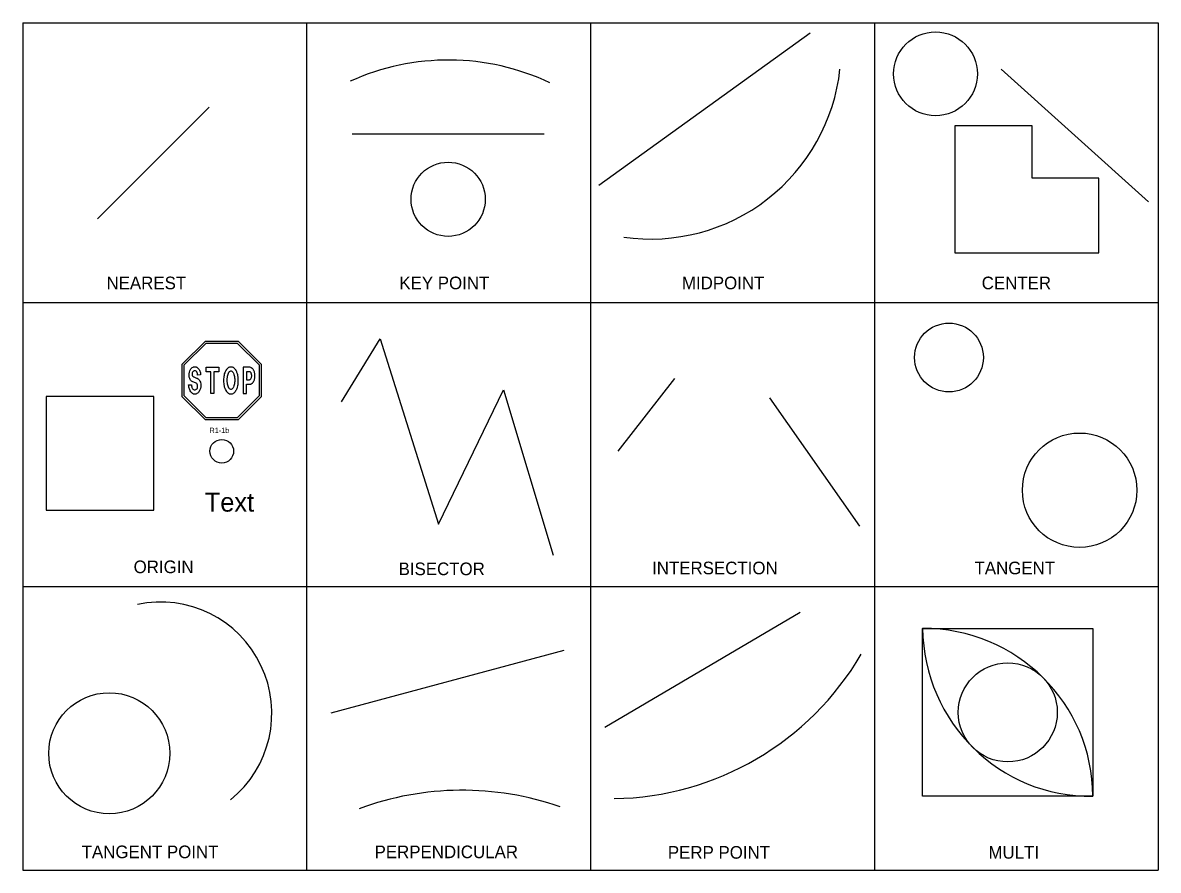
# Model space of a CAD drawing. Extents: x 0 to 180, y 0 to 134.
import ezdxf

# ---------------------------------------------------------------- set-up
doc = ezdxf.new("R2010")
doc.units = 0
for name, color, linetype in [('Default', 7, 'Continuous'), ('Level 1', 7, 'Continuous'), ('Level 2', 7, 'Continuous'), ('Level 3', 7, 'Continuous')]:
    doc.layers.add(name, color=color, linetype=linetype)

# ---------------------------------------------------------------- blocks, each defined once
blk = doc.blocks.new('R11B')
at = {"layer": 'Default'}
for p, q in [((-1.25, 2.762), (-0.518, 3.494)), ((-1.187, 2.736), (-0.492, 3.431)), ((-0.518, 3.494), (0.518, 3.494)), ((-0.492, 3.431), (0.492, 3.431)), ((0.492, 3.431), (1.187, 2.736)), ((0.518, 3.494), (1.25, 2.762)), ((-1.25, 1.726), (-1.25, 2.762)), ((-1.187, 1.752), (-1.187, 2.736)), ((1.187, 2.736), (1.187, 1.752)), ((1.25, 2.762), (1.25, 1.726)), ((-0.518, 0.994), (-1.25, 1.726)), ((-0.492, 1.056), (-1.187, 1.752)), ((1.187, 1.752), (0.492, 1.056)), ((1.25, 1.726), (0.518, 0.994)), ((0.518, 0.994), (-0.518, 0.994)), ((0.492, 1.056), (-0.492, 1.056))]:
    blk.add_line(p, q, dxfattribs=at)
for points in [[(-0.764, 2.044), (-0.764, 2.063), (-0.764, 2.096), (-0.775, 2.129), (-0.795, 2.149), (-0.814, 2.162), (-0.937, 2.214), (-0.96, 2.227), (-0.986, 2.254), (-1.002, 2.28), (-1.017, 2.306), (-1.029, 2.352), (-1.033, 2.392), (-1.033, 2.451), (-1.025, 2.503), (-1.013, 2.549), (-0.994, 2.588), (-0.979, 2.608)], [(-0.979, 2.608), (-0.967, 2.621), (-0.956, 2.634), (-0.948, 2.641), (-0.933, 2.654), (-0.91, 2.667), (-0.894, 2.674), (-0.867, 2.68), (-0.86, 2.68), (-0.844, 2.68), (-0.814, 2.674), (-0.802, 2.667), (-0.791, 2.661), (-0.772, 2.647), (-0.756, 2.634), (-0.748, 2.628), (-0.737, 2.615)], [(-0.764, 2.411), (-0.768, 2.464), (-0.775, 2.49), (-0.787, 2.516), (-0.798, 2.529), (-0.814, 2.542), (-0.837, 2.549), (-0.86, 2.549), (-0.879, 2.549), (-0.891, 2.542), (-0.906, 2.529), (-0.925, 2.51), (-0.937, 2.49), (-0.94, 2.464), (-0.94, 2.444)], [(-0.737, 2.615), (-0.718, 2.588), (-0.706, 2.569), (-0.695, 2.536), (-0.687, 2.516), (-0.679, 2.483), (-0.676, 2.451), (-0.672, 2.418), (-0.764, 2.411)], [(-0.499, 2.661), (-0.096, 2.661), (-0.096, 2.523), (-0.246, 2.523), (-0.246, 1.827), (-0.349, 1.827), (-0.349, 2.523), (-0.499, 2.523), (-0.499, 2.661)], [(0.069, 2.241), (0.069, 2.26), (0.069, 2.293), (0.073, 2.339), (0.077, 2.378), (0.084, 2.411), (0.092, 2.451), (0.104, 2.483), (0.111, 2.51), (0.119, 2.529), (0.13, 2.549), (0.157, 2.595), (0.161, 2.602), (0.173, 2.615), (0.184, 2.628), (0.196, 2.641), (0.203, 2.647), (0.223, 2.661), (0.238, 2.667), (0.253, 2.674), (0.292, 2.68)], [(0.173, 2.254), (0.173, 2.267), (0.173, 2.293), (0.173, 2.313), (0.177, 2.339), (0.18, 2.365), (0.184, 2.385), (0.188, 2.411), (0.2, 2.444), (0.211, 2.477), (0.215, 2.483), (0.223, 2.497), (0.23, 2.51), (0.238, 2.516), (0.249, 2.529), (0.269, 2.542), (0.284, 2.549), (0.296, 2.549), (0.303, 2.549), (0.315, 2.542), (0.326, 2.536), (0.342, 2.523), (0.361, 2.497), (0.372, 2.477), (0.388, 2.437), (0.395, 2.405), (0.403, 2.365), (0.407, 2.332), (0.411, 2.3), (0.411, 2.267), (0.411, 2.254)], [(0.288, 2.68), (0.307, 2.68), (0.334, 2.674), (0.349, 2.667), (0.361, 2.661), (0.388, 2.641), (0.411, 2.615), (0.43, 2.588), (0.453, 2.549), (0.464, 2.529), (0.472, 2.51), (0.48, 2.483), (0.487, 2.464), (0.495, 2.431), (0.503, 2.392), (0.507, 2.365), (0.51, 2.339), (0.514, 2.3), (0.514, 2.28), (0.514, 2.241)], [(0.894, 2.661), (0.683, 2.661), (0.683, 1.827), (0.787, 1.827), (0.787, 2.123), (0.894, 2.123)], [(0.871, 2.523), (0.787, 2.523), (0.787, 2.267), (0.871, 2.267)], [(0.871, 2.267), (0.879, 2.267), (0.894, 2.273), (0.906, 2.28), (0.914, 2.287), (0.925, 2.3), (0.933, 2.313), (0.937, 2.319), (0.944, 2.339), (0.948, 2.359), (0.952, 2.385), (0.952, 2.398), (0.948, 2.431), (0.944, 2.451), (0.937, 2.47), (0.929, 2.483), (0.921, 2.497), (0.914, 2.503), (0.906, 2.51), (0.898, 2.516), (0.879, 2.523), (0.875, 2.523), (0.871, 2.523)], [(0.894, 2.123), (0.917, 2.129), (0.933, 2.136), (0.944, 2.142), (0.956, 2.149), (0.963, 2.155), (0.971, 2.162), (0.983, 2.175), (0.994, 2.188), (1.002, 2.201), (1.01, 2.214), (1.017, 2.227), (1.025, 2.247), (1.033, 2.267), (1.036, 2.28), (1.04, 2.293), (1.044, 2.313), (1.048, 2.332), (1.052, 2.365), (1.052, 2.385), (1.052, 2.411), (1.048, 2.444), (1.048, 2.451), (1.044, 2.47), (1.04, 2.49), (1.033, 2.516), (1.025, 2.536), (1.017, 2.556), (1.01, 2.569), (1.002, 2.582), (0.994, 2.595), (0.983, 2.608), (0.971, 2.621), (0.963, 2.628), (0.956, 2.634), (0.944, 2.641), (0.937, 2.647), (0.917, 2.654), (0.894, 2.661)], [(-0.94, 2.444), (-0.94, 2.424), (-0.933, 2.405), (-0.925, 2.392), (-0.914, 2.378), (-0.887, 2.359), (-0.802, 2.319), (-0.783, 2.313), (-0.752, 2.3), (-0.729, 2.28), (-0.714, 2.26), (-0.702, 2.247), (-0.691, 2.221), (-0.679, 2.195), (-0.676, 2.175), (-0.668, 2.136), (-0.664, 2.109), (-0.664, 2.09), (-0.664, 2.057), (-0.668, 2.024), (-0.672, 1.998), (-0.676, 1.991)], [(0.514, 2.241), (0.514, 2.195), (0.51, 2.136), (0.507, 2.109), (0.499, 2.077), (0.491, 2.037), (0.484, 2.011), (0.476, 1.991), (0.464, 1.958), (0.453, 1.939), (0.441, 1.913), (0.422, 1.886), (0.411, 1.873), (0.399, 1.86), (0.38, 1.84), (0.361, 1.827), (0.349, 1.821), (0.326, 1.814), (0.303, 1.808), (0.296, 1.808), (0.276, 1.808), (0.249, 1.814), (0.238, 1.821), (0.223, 1.827), (0.215, 1.834), (0.203, 1.84), (0.196, 1.847), (0.184, 1.86), (0.165, 1.88), (0.157, 1.893), (0.127, 1.945), (0.119, 1.958), (0.107, 1.991), (0.1, 2.011), (0.092, 2.037), (0.084, 2.077), (0.081, 2.096), (0.077, 2.123), (0.073, 2.149), (0.069, 2.188), (0.069, 2.221), (0.069, 2.241)], [(0.296, 1.958), (0.284, 1.958), (0.269, 1.965), (0.249, 1.978), (0.238, 1.991), (0.23, 1.998), (0.223, 2.011), (0.215, 2.024), (0.211, 2.031), (0.2, 2.063), (0.188, 2.096), (0.184, 2.123), (0.18, 2.142), (0.177, 2.168), (0.173, 2.195), (0.173, 2.214), (0.173, 2.241), (0.173, 2.254)], [(0.411, 2.254), (0.411, 2.241), (0.411, 2.208), (0.407, 2.175), (0.403, 2.142), (0.395, 2.103), (0.388, 2.07), (0.372, 2.031), (0.361, 2.011), (0.342, 1.985), (0.326, 1.972), (0.315, 1.965), (0.303, 1.958), (0.296, 1.958)], [(-1.052, 2.103), (-0.956, 2.109), (-0.956, 2.09)], [(-0.676, 1.991), (-0.683, 1.972), (-0.691, 1.952), (-0.702, 1.926), (-0.71, 1.913), (-0.722, 1.893), (-0.729, 1.88), (-0.741, 1.867), (-0.752, 1.853), (-0.768, 1.84), (-0.787, 1.827), (-0.798, 1.821), (-0.818, 1.814), (-0.844, 1.808), (-0.856, 1.808), (-0.867, 1.808), (-0.894, 1.814), (-0.91, 1.821), (-0.917, 1.827), (-0.929, 1.834), (-0.937, 1.84), (-0.952, 1.853), (-0.96, 1.86), (-0.979, 1.886), (-0.998, 1.913), (-1.013, 1.945), (-1.017, 1.952), (-1.025, 1.978), (-1.033, 1.998), (-1.036, 2.011), (-1.04, 2.024), (-1.044, 2.05), (-1.048, 2.077), (-1.052, 2.103)], [(-0.956, 2.09), (-0.956, 2.07), (-0.952, 2.044), (-0.948, 2.024), (-0.94, 2.004), (-0.929, 1.985), (-0.917, 1.972), (-0.894, 1.958), (-0.871, 1.952), (-0.86, 1.952), (-0.841, 1.952), (-0.821, 1.958), (-0.806, 1.965)], [(-0.806, 1.965), (-0.779, 1.985), (-0.772, 1.998), (-0.764, 2.024), (-0.764, 2.044)]]:
    blk.add_lwpolyline(points, dxfattribs=at)
blk.add_circle((0, 0), 0.375, dxfattribs=at)
blk.add_text('R1-1b', height=0.1667, dxfattribs=at).set_placement((-0.389, 0.579))

msp = doc.modelspace()

# ---------------------------------------------------------------- linework, layer by layer
at = {"layer": 'Level 1'}
for p, q in [((91.32, 108.59), (124.8, 132.73)), ((155.09, 127), (178.43, 105.98)), ((11.86, 103.28), (29.53, 120.96)), ((52.2, 116.73), (82.68, 116.73)), ((94.38, 66.44), (103.39, 77.95)), ((118.37, 74.91), (132.66, 54.54)), ((92.28, 22.66), (123.23, 40.94)), ((48.89, 24.97), (85.8, 34.88))]:
    msp.add_line(p, q, dxfattribs=at)
for points in [[(147.75, 117.99), (147.75, 97.85), (170.56, 97.85), (170.56, 109.73), (160.01, 109.73), (160.01, 117.99)], [(20.8, 75.12), (3.73, 75.12), (3.73, 57.1), (20.8, 57.1)]]:
    msp.add_lwpolyline(points, close=True, dxfattribs=at)
msp.add_lwpolyline([(50.54, 74.26), (56.65, 84.22), (65.91, 54.85), (76.22, 76.18), (84.09, 49.95)], dxfattribs=at)
for centre, radius in [((144.69, 126.24), 6.65), ((67.44, 106.36), 5.88), ((146.82, 81.28), 5.45), ((167.53, 60.24), 9.07), ((13.72, 18.55), 9.59)]:
    msp.add_circle(centre, radius, dxfattribs=at)
for centre, radius, start, end in [((67.47, 90.81), 37.62, 64.6474, 114.4477), ((99.51, 130.26), 30.21, 261.9238, 353.7839), ((21.84, 24.88), 17.64, 308.9275, 101.9402), ((93, 57.58), 46.23, 270.9492, 329.6843), ((69.66, -34.14), 46.83, 70.6206, 110.3838)]:
    msp.add_arc(centre, radius, start, end, dxfattribs=at)
at = {"layer": 'Level 2'}
for p, q in [((0, 134.35), (0, 0)), ((0, 134.35), (180, 134.35)), ((45, 134.35), (45, 0)), ((90, 134.35), (90, 0)), ((135, 134.35), (135, 0)), ((180, 134.35), (180, 0)), ((0, 90), (180, 90)), ((0, 45), (180, 45)), ((0, 0), (180, 0))]:
    msp.add_line(p, q, dxfattribs=at)
at = {"layer": 'Level 3'}
msp.add_lwpolyline([(142.65, 38.35), (169.61, 38.35), (169.61, 11.73), (142.65, 11.73)], close=True, dxfattribs=at)
msp.add_circle((156.14, 25.03), 7.85, dxfattribs=at)
for centre, major_axis, start_param, end_param in [((142.65, 11.73), (26.96, 0), 0, 1.570796), ((169.27, 38.69), (0.34, -26.96), 4.712389, 6.283185)]:
    msp.add_ellipse(centre, major_axis=major_axis, ratio=0.987421, start_param=start_param, end_param=end_param, dxfattribs=at)

# ---------------------------------------------------------------- block references
at = {"layer": 'Level 1', "xscale": 4.99999992, "yscale": 4.99999992}
msp.add_blockref('R11B', (31.55, 66.42), dxfattribs=at)

# ---------------------------------------------------------------- texts
at = {"layer": 'Level 1'}
msp.add_text('Text', height=3, dxfattribs=at).set_placement((28.87, 56.85))
at = {"layer": 'Level 3'}
for s, p in [('NEAREST', (13.28, 92.1)), ('KEY POINT', (59.7, 92.1)), ('MIDPOINT', (104.49, 92.1)), ('CENTER', (152.01, 92.1)), ('ORIGIN', (17.58, 47.1)), ('BISECTOR', (59.58, 46.78)), ('INTERSECTION', (99.76, 46.92)), ('TANGENT', (150.87, 46.92)), ('TANGENT POINT', (9.34, 1.92)), ('PERPENDICULAR', (55.77, 1.92)), ('PERP POINT', (102.26, 1.84)), ('MULTI', (153.08, 1.84))]:
    msp.add_text(s, height=2, dxfattribs=at).set_placement(p)

doc.saveas('drawing.dxf')
